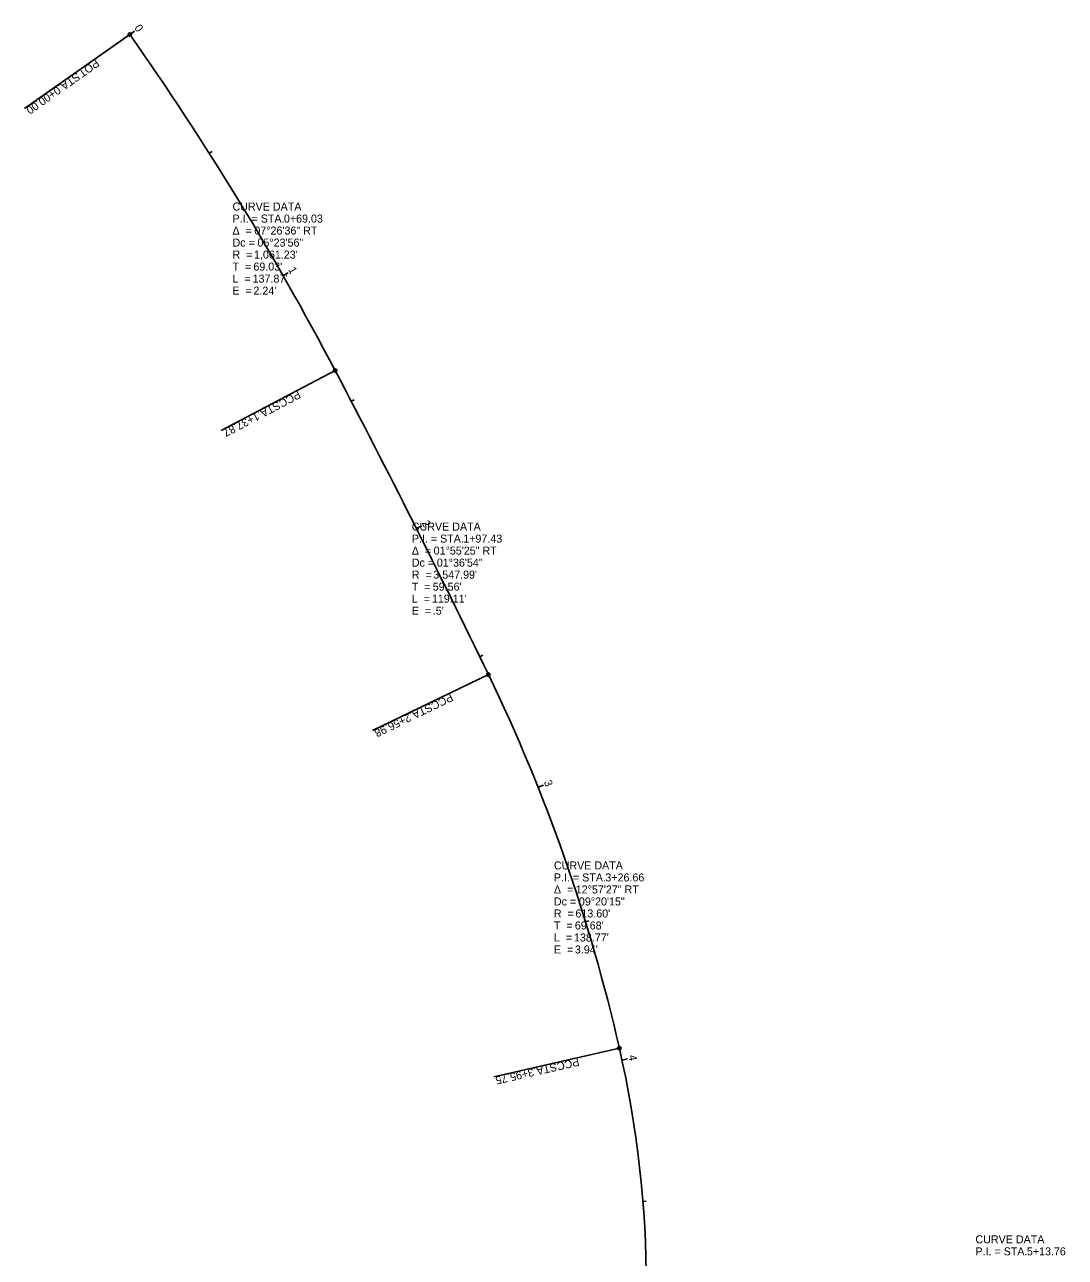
# Model space of a CAD drawing. Extents: x 2376685 to 2377050, y 700343 to 701208.
# Drawn here: x 2376685.4 to 2377049.6, y 700776.9 to 701208.1 of the extents above; entities that cross this region are included whole.
import ezdxf

# ---------------------------------------------------------------- set-up
doc = ezdxf.new("R2010")
doc.units = 0
for name, color, linetype in [('GE_X_Alignment', 7, 'Continuous'), ('GE_X_Alignment_100_Cardinal_Points', 7, 'Continuous'), ('GE_X_Alignment_100_Curve_Data', 7, 'Continuous'), ('GE_X_Alignment_100_Stations', 7, 'Continuous')]:
    doc.layers.add(name, color=color, linetype=linetype)

msp = doc.modelspace()

# ---------------------------------------------------------------- linework, layer by layer
at = {"layer": 'GE_X_Alignment'}
for centre, radius, start, end in [((2375854.64, 700593.42), 1061.23, 27.72153, 35.16498), ((2373653.32, 699436.65), 3547.99, 25.79802, 27.72153), ((2376295.25, 700713.69), 613.6, 12.84046, 25.79802), ((2376524.38, 700765.92), 378.59, 322.1906, 12.8405)]:
    msp.add_arc(centre, radius, start, end, dxfattribs=at)
at = {"layer": 'GE_X_Alignment_100_Cardinal_Points'}
for p, q in [((2376722.2, 701204.62), (2376685.41, 701178.71)), ((2376794.06, 701087.08), (2376754.23, 701066.15)), ((2376847.69, 700980.73), (2376807.18, 700961.15)), ((2376893.5, 700850.06), (2376849.63, 700840.06))]:
    msp.add_line(p, q, dxfattribs=at)
for centre in [(2376722.2, 701204.62), (2376794.06, 701087.08), (2376847.69, 700980.73), (2376893.5, 700850.06)]:
    msp.add_circle(centre, 0.6, dxfattribs=at)
at = {"layer": 'GE_X_Alignment_100_Stations'}
for p, q in [((2376722.2, 701204.62), (2376723.83, 701205.77)), ((2376750.02, 701163.08), (2376751.03, 701163.73)), ((2376775.86, 701120.28), (2376777.59, 701121.28)), ((2376799.69, 701076.33), (2376800.75, 701076.89)), ((2376822.48, 701031.83), (2376824.27, 701032.73)), ((2376844.65, 700987.01), (2376845.73, 700987.54)), ((2376865.04, 700941.37), (2376866.9, 700942.12)), ((2376881.68, 700894.24), (2376882.83, 700894.59)), ((2376894.43, 700845.91), (2376896.38, 700846.33)), ((2376901.74, 700796.48), (2376902.93, 700796.58))]:
    msp.add_line(p, q, dxfattribs=at)

# ---------------------------------------------------------------- texts
at = {"layer": 'GE_X_Alignment_100_Cardinal_Points'}
for s, rotation, p in [('POT', 215.165, (2376710.25, 701196.16)), (' STA. ', 215.165, (2376704.43, 701192.06)), ('0+00.00', 215.165, (2376696.8, 701186.69)), ('PCC', 207.7215, (2376781.03, 701080.19)), (' STA. ', 207.7215, (2376774.87, 701076.95)), ('1+37.87', 207.7215, (2376766.62, 701072.62)), ('PCC', 205.798, (2376834.44, 700974.29)), (' STA. ', 205.798, (2376828.17, 700971.26)), ('2+56.98', 205.798, (2376819.78, 700967.2)), ('3+95.75', 192.8405, (2376863.23, 700843.12)), (' STA. ', 192.8405, (2376872.32, 700845.19)), ('PCC', 192.8405, (2376879.1, 700846.74))]:
    msp.add_text(s, height=2.8, rotation=rotation, dxfattribs=at).set_placement(p)
at = {"layer": 'GE_X_Alignment_100_Curve_Data'}
for s, p in [('CURVE DATA', (2376758.13, 701143.05)), ('P.I. = STA. ', (2376758.13, 701138.85)), ('0+69.03', (2376776.12, 701138.85)), ('Δ  = ', (2376758.13, 701134.65)), ('07°26\'36" RT', (2376765.78, 701134.65)), ('Dc = ', (2376758.13, 701130.45)), ('05°23\'56"', (2376766.87, 701130.45)), ('R  = ', (2376758.13, 701126.25)), ("1,061.23'", (2376765.67, 701126.25)), ('T  = ', (2376758.13, 701122.05)), ("69.03'", (2376765.45, 701122.05)), ('L  = ', (2376758.13, 701117.85)), ("137.87'", (2376765.17, 701117.85)), ('E  = ', (2376758.13, 701113.65)), ("2.24'", (2376765.47, 701113.65)), ('CURVE DATA', (2376820.88, 701031.11)), ('P.I. = STA. ', (2376820.88, 701026.91)), ('1+97.43', (2376838.87, 701026.91)), ('Δ  = ', (2376820.88, 701022.71)), ('01°55\'25" RT', (2376828.52, 701022.71)), ('Dc = ', (2376820.88, 701018.51)), ('01°36\'54"', (2376829.62, 701018.51)), ('R  = ', (2376820.88, 701014.31)), ("3,547.99'", (2376828.41, 701014.31)), ('T  = ', (2376820.88, 701010.11)), ("59.56'", (2376828.2, 701010.11)), ('L  = ', (2376820.88, 701005.91)), ("119.11'", (2376827.91, 701005.91)), ('E  = ', (2376820.88, 701001.71)), (".5'", (2376828.22, 701001.71)), ('CURVE DATA', (2376870.6, 700912.6)), ('P.I. = STA. ', (2376870.6, 700908.4)), ('3+26.66', (2376888.59, 700908.4)), ('Δ  = ', (2376870.6, 700904.2)), ('12°57\'27" RT', (2376878.24, 700904.2)), ('Dc = ', (2376870.6, 700900)), ("613.60'", (2376878.13, 700895.8)), ('09°20\'15"', (2376879.34, 700900)), ('T  = ', (2376870.6, 700891.6)), ('R  = ', (2376870.6, 700895.8)), ("69.68'", (2376877.92, 700891.6)), ('L  = ', (2376870.6, 700887.4)), ("138.77'", (2376877.63, 700887.4)), ('E  = ', (2376870.6, 700883.2)), ("3.94'", (2376877.94, 700883.2)), ('CURVE DATA', (2377018.09, 700781.82)), ('P.I. = STA. ', (2377018.09, 700777.62)), ('5+13.76', (2377036.08, 700777.62))]:
    msp.add_text(s, height=2.8, dxfattribs=at).set_placement(p)
at = {"layer": 'GE_X_Alignment_100_Stations'}
for s, rotation, p in [('0', 305.165, (2376723.64, 701206.91)), ('1', 299.766, (2376777.53, 701122.38)), ('2', 296.7182, (2376824.28, 701033.83)), ('3', 291.7809, (2376867.01, 700943.2)), ('4', 282.1967, (2376896.65, 700847.46))]:
    msp.add_text(s, height=2.8, rotation=rotation, dxfattribs=at).set_placement(p)

doc.saveas('drawing.dxf')
